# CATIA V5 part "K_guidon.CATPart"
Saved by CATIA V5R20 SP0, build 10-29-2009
Part number: guidon
Bounding box of the stored display mesh (mm): x -30 to 30, y -25 to 25, z 7.5 to 415
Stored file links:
  G:\Khaled_CFAO_2011\SIL\SIL_GR2\ahabrial\ahabrial\Khaled\CAD_ThinkMOTION\K_guidon.CATPart
  G:\Données\Ecole\IFMA\2A\Thinkmotion2\Etape18\trotinette.CATProduct
  G:\Khaled_CFAO_2011\SIL\SIL_GR2\ahabrial\ahabrial\Khaled\CAD_ThinkMOTION\K_bati.CATPart
  G:\Khaled_CFAO_2011\SIL\SIL_GR2\ahabrial\ahabrial\Etape18\skl_guidon.CATPart
  G:\Khaled_CFAO_2011\SIL\SIL_GR2\ahabrial\ahabrial\Khaled\CAD_ThinkMOTION\K_skl_guidon_haut.CATPart
  G:\Khaled_CFAO_2011\SIL\SIL_GR2\ahabrial\ahabrial\Khaled\CAD_ThinkMOTION\K_avant.CATPart
  G:\Khaled_CFAO_2011\SIL\SIL_GR2\ahabrial\ahabrial\Khaled\CAD_ThinkMOTION\K_skl_bati.CATPart
  G:\Khaled_CFAO_2011\SIL\SIL_GR2\ahabrial\ahabrial\Khaled\CAD_ThinkMOTION\K_frein.CATPart
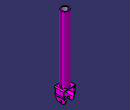
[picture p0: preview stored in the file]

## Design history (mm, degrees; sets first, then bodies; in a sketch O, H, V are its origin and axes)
Parameters
  Diametre_guidon = 75 mm
  Epaisseur_accroche_guidon_avant = 5 mm
  Diametre_axe_guidon_avant = 20 mm
External parameters (linked from other documents)
  `External.Longueur_coté_pivot_avant` = 30 mm
  External.Diametre_bati = 60 mm
  External.Diametre_guidondsbati = 40 mm
  External.hauteur_guidon = 200 mm
  External.hauteur_bati = 170 mm
  External.Diametre_guidon_haut = 30 mm
  External.Longueur_guidon = 300 mm
  External.Diametre_pivot_avant = 10 mm
  External.Hauteur_bati2 = 100 mm
Set1
  Plane1 "Plan_bati_guidon": linked copy from another document
  Point1 "Point.1_bati_guidon": linked copy from another document
  Plane2: linked copy from another document
  Line1: linked copy from another document
  Point2 "Point.3_guidon_bati": linked copy from another document
  Point3 "Point.1_origine": linked copy from another document
Body1 (main body)
  Sketch1 on Plane2, origin (0, 0, 0), H (-1, 0, 0), V (0, 0, 1)
    construction line L1 (0, 75) -> (0, -20)
    point P1 (0, 75)
    construction line L2 (40, 0) -> (-20, 0)
    line L3 (17.5, 7.5) -> (17.5, 30)
    point P5 (17.5, 7.5)
    point P6 (17.5, 30)
    line L4 (25, 40) -> (25, 70)
    point P7 (25, 40)
    point P8 (25, 70)
    construction line L5 (25, 40) -> (-35, 40)
    point P9 (25, 40)
    axis line L6 (47.5, 30) -> (17.5, 30)
    point P12 (17.5, 30)
    spline S1 through (17.5, 30) (25, 40)
    line L7 (25, 70) -> (0, 70)
    point P13 (0, 70)
    point P14 (0, 70)
    point P15 (-25, 70)
    line L8 (-25, 70) -> (0, 70)
    point P16 (-25, 40)
    line L9 (-25, 40) -> (-25, 70)
    spline S2 through (-17.5, 30) (-25, 40)
    point P17 (-17.5, 30)
    point P18 (-17.5, 7.5)
    line L10 (-17.5, 7.5) -> (-17.5, 30)
    line L11 (22.5, 7.5) -> (22.5, 30)
    point P19 (22.5, 30)
    point P20 (22.5, 7.5)
    line L12 (30, 40) -> (30, 75)
    point P21 (30, 40)
    point P22 (30, 75)
    line L13 (30, 75) -> (0, 75)
    spline S3 through (22.5, 30) (30, 40)
    line L14 (22.5, 7.5) -> (17.5, 7.5)
    point P23 (0, 75)
    point P24 (-30, 75)
    line L15 (-30, 75) -> (0, 75)
    point P25 (-30, 40)
    line L16 (-30, 40) -> (-30, 75)
    spline S4 through (-22.5, 30) (-30, 40)
    point P26 (-22.5, 30)
    point P27 (-22.5, 7.5)
    line L17 (-22.5, 7.5) -> (-22.5, 30)
    point P28 (-17.5, 7.5)
    line L18 (-22.5, 7.5) -> (-17.5, 7.5)
    point P29 (17.5, 30)
    point P30 (25, 40)
    point P31 (-25, 40)
    point P32 (-17.5, 30)
    point P33 (22.5, 30)
    point P34 (30, 40)
    point P35 (-30, 40)
    point P36 (-22.5, 30)
    length L3 = 22.5 {= `External.Longueur_coté_pivot_avant` *(3/4)}
    distance L2 P5 = 7.5 {= `External.Longueur_coté_pivot_avant` /4}
    distance L1 L3 = 17.5 {= (`External.Longueur_coté_pivot_avant` /2)+(Epaisseur_accroche_guidon_avant /2)}
    distance L4 L1 = 25 {= (External.Diametre_bati /2)-Epaisseur_accroche_guidon_avant}
    length L4 = 30 {= `External.Longueur_coté_pivot_avant`}
    distance L5 L6 = 10 {= `External.Longueur_coté_pivot_avant` /3}
    length L12 = 35 {= `External.Longueur_coté_pivot_avant` +Epaisseur_accroche_guidon_avant}
    distance L4 L12 = 5 {= Epaisseur_accroche_guidon_avant}
    distance L3 L11 = 5 {= Epaisseur_accroche_guidon_avant}
    coincidence: P1 V, P9 P7, P12 P6, P29 P6, P30 P7, P13 L1, P19 L6, P21 L5, P33 P19, P34 P21, P1 P23, P13 P14, P16 P31, P32 P17, P18 P28, P25 P35, P36 P26
    vertical: L1 V, L3 V, L4 V, L11 V, L12 V
    horizontal: L2 H, L5 H, L6 H, L7 H, L13 H, L14 H
    fix: L2
    symmetry: P13 P14 L1, P8 P15 L1, L7 L8 L1, P7 P16 L1, L4 L9 L1, S1 S2 L1, P6 P17 L1, P5 P18 L1, L3 L10 L1, P30 P31 L1, P29 P32 L1, P1 P23 L1, P22 P24 L1, L13 L15 L1, P21 P25 L1, L12 L16 L1, S3 S4 L1, P19 P26 L1, P20 P27 L1, L11 L17 L1, P5 P28 L1, L14 L18 L1, P34 P35 L1, P33 P36 L1
  Pad1: profile Sketch1, direction (0, 1, 0), length 25 {= `External.Longueur_coté_pivot_avant` /2 +10mm}, mirrored extent
  Plane3 "Plan_guidon_sur_accroche": type Offset, RefPlane face of Pad1 from Sketch1.L15, Offset 0, reversed
  Sketch2 on face of Pad1 from Sketch1.L16, origin (30, 0, 0), H (0, 1, 0), V (0, 0, 1)
    spline S1 through (-25, 75) (-20.4189, 49.4327) (-22.4122, 16.5178) (0, 7.5)
    reference projected point E1 (-25, 75) from vertex [face of Pad1 from Sketch1.L16 | start face of Pad1 | face of Pad1 from Sketch1.L15]
    reference projected line E2 (-25, 7.5) -> (25, 7.5) from edge [face of Pad1 from Sketch1.L18 | face of Pad1 from Sketch1.L17]
    reference projected line E3 (0, 370) -> (0, 0) from Line1
    reference projected line E4 (0, 370) -> (0, 0) from edge of Line1
    spline S2 through (25, 75) (20.4189, 49.4327) (22.4122, 16.5178) (0, 7.5)
    line L1 (25, 75) -> (-25, 75)
    point P3 (25, 75)
    point P4 (-25, 75)
    point P5 (-25, 75)
    point P6 (0, 7.5)
    point P7 (0, 7.5)
    point P8 (25, 75)
    point P9 (-22.4122, 16.5178)
    point P10 (22.4122, 16.5178)
    point P11 (-20.4189, 49.4327)
    point P12 (20.4189, 49.4327)
    coincidence: E1 P5, E2 P6, E3 P6, P8 P3, P5 P4, P6 P7
    symmetry: S1 S2 E4, P6 P7 E4, P5 P8 E4, P9 P10 E4, P11 P12 E4
    tangency: S1 S2
    horizontal: L1 H
  Pocket1: profile Sketch2, direction (-1, 0, 0), through (limit type 6), outer side
  Fillet1: radius 19, on edge [face of Pad1 from Sketch1.S4 | face of Pad1 from Sketch1.L16]
  Fillet2: radius 5, on edge [face of Pocket1 | face of Pad1 from Sketch1.L16]
  Sketch3 on face of Pad1 from Sketch1.L17, origin (22.5, 9.3172, 20.1463), H (0, 1, 0), V (0, 0, 1)
    point P1 (-9.3172, -5.1463)
    reference projected line E1 (-9.3172, 349.8537) -> (-9.3172, -20.1463) from Line1
    reference projected line E2 (-34.3172, 9.8537) -> (15.6828, 9.8537) from edge [face of Pad1 from Sketch1.L17 | face of Pad1 from Sketch1.S4]
    distance E2 P1 = 15 {= `External.Longueur_coté_pivot_avant` /2}
    coincidence: P1 E1
  Hole1: placed by Sketch3, at (22.5, 0, 15) direction (-1, 0, 0), diameter 10 {= External.Diametre_pivot_avant}, through (limit type 3)
  Sketch4 on face of Pad1, origin (0, 0, 75), H (1, 0, 0), V (0, 1, 0)
    circle A1 centre (0, 0) radius 20
    point P1 (0, 0)
    reference projected point E1 (0, 0) from Point2
    radius A1 = 20 {= External.Diametre_guidondsbati /2}
    coincidence: P1 E1
  Pad2: profile Sketch4, direction (0, 0, 1), length 340 {= External.hauteur_bati *2}
  Sketch5 on end face of Pad2, origin (0, 0, 415), H (1, 0, 0), V (0, 1, 0)
    circle A1 centre (0, 0) radius 15
    point P1 (0, 0)
    reference projected point E1 (0, 0) from Point3
    radius A1 = 15 {= External.Diametre_guidon_haut /2}
    coincidence: P1 E1
  Pocket2: profile Sketch5, direction (0, 0, -1), length 170 {= External.hauteur_bati}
